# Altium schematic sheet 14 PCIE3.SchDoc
size 420 x 297 mm
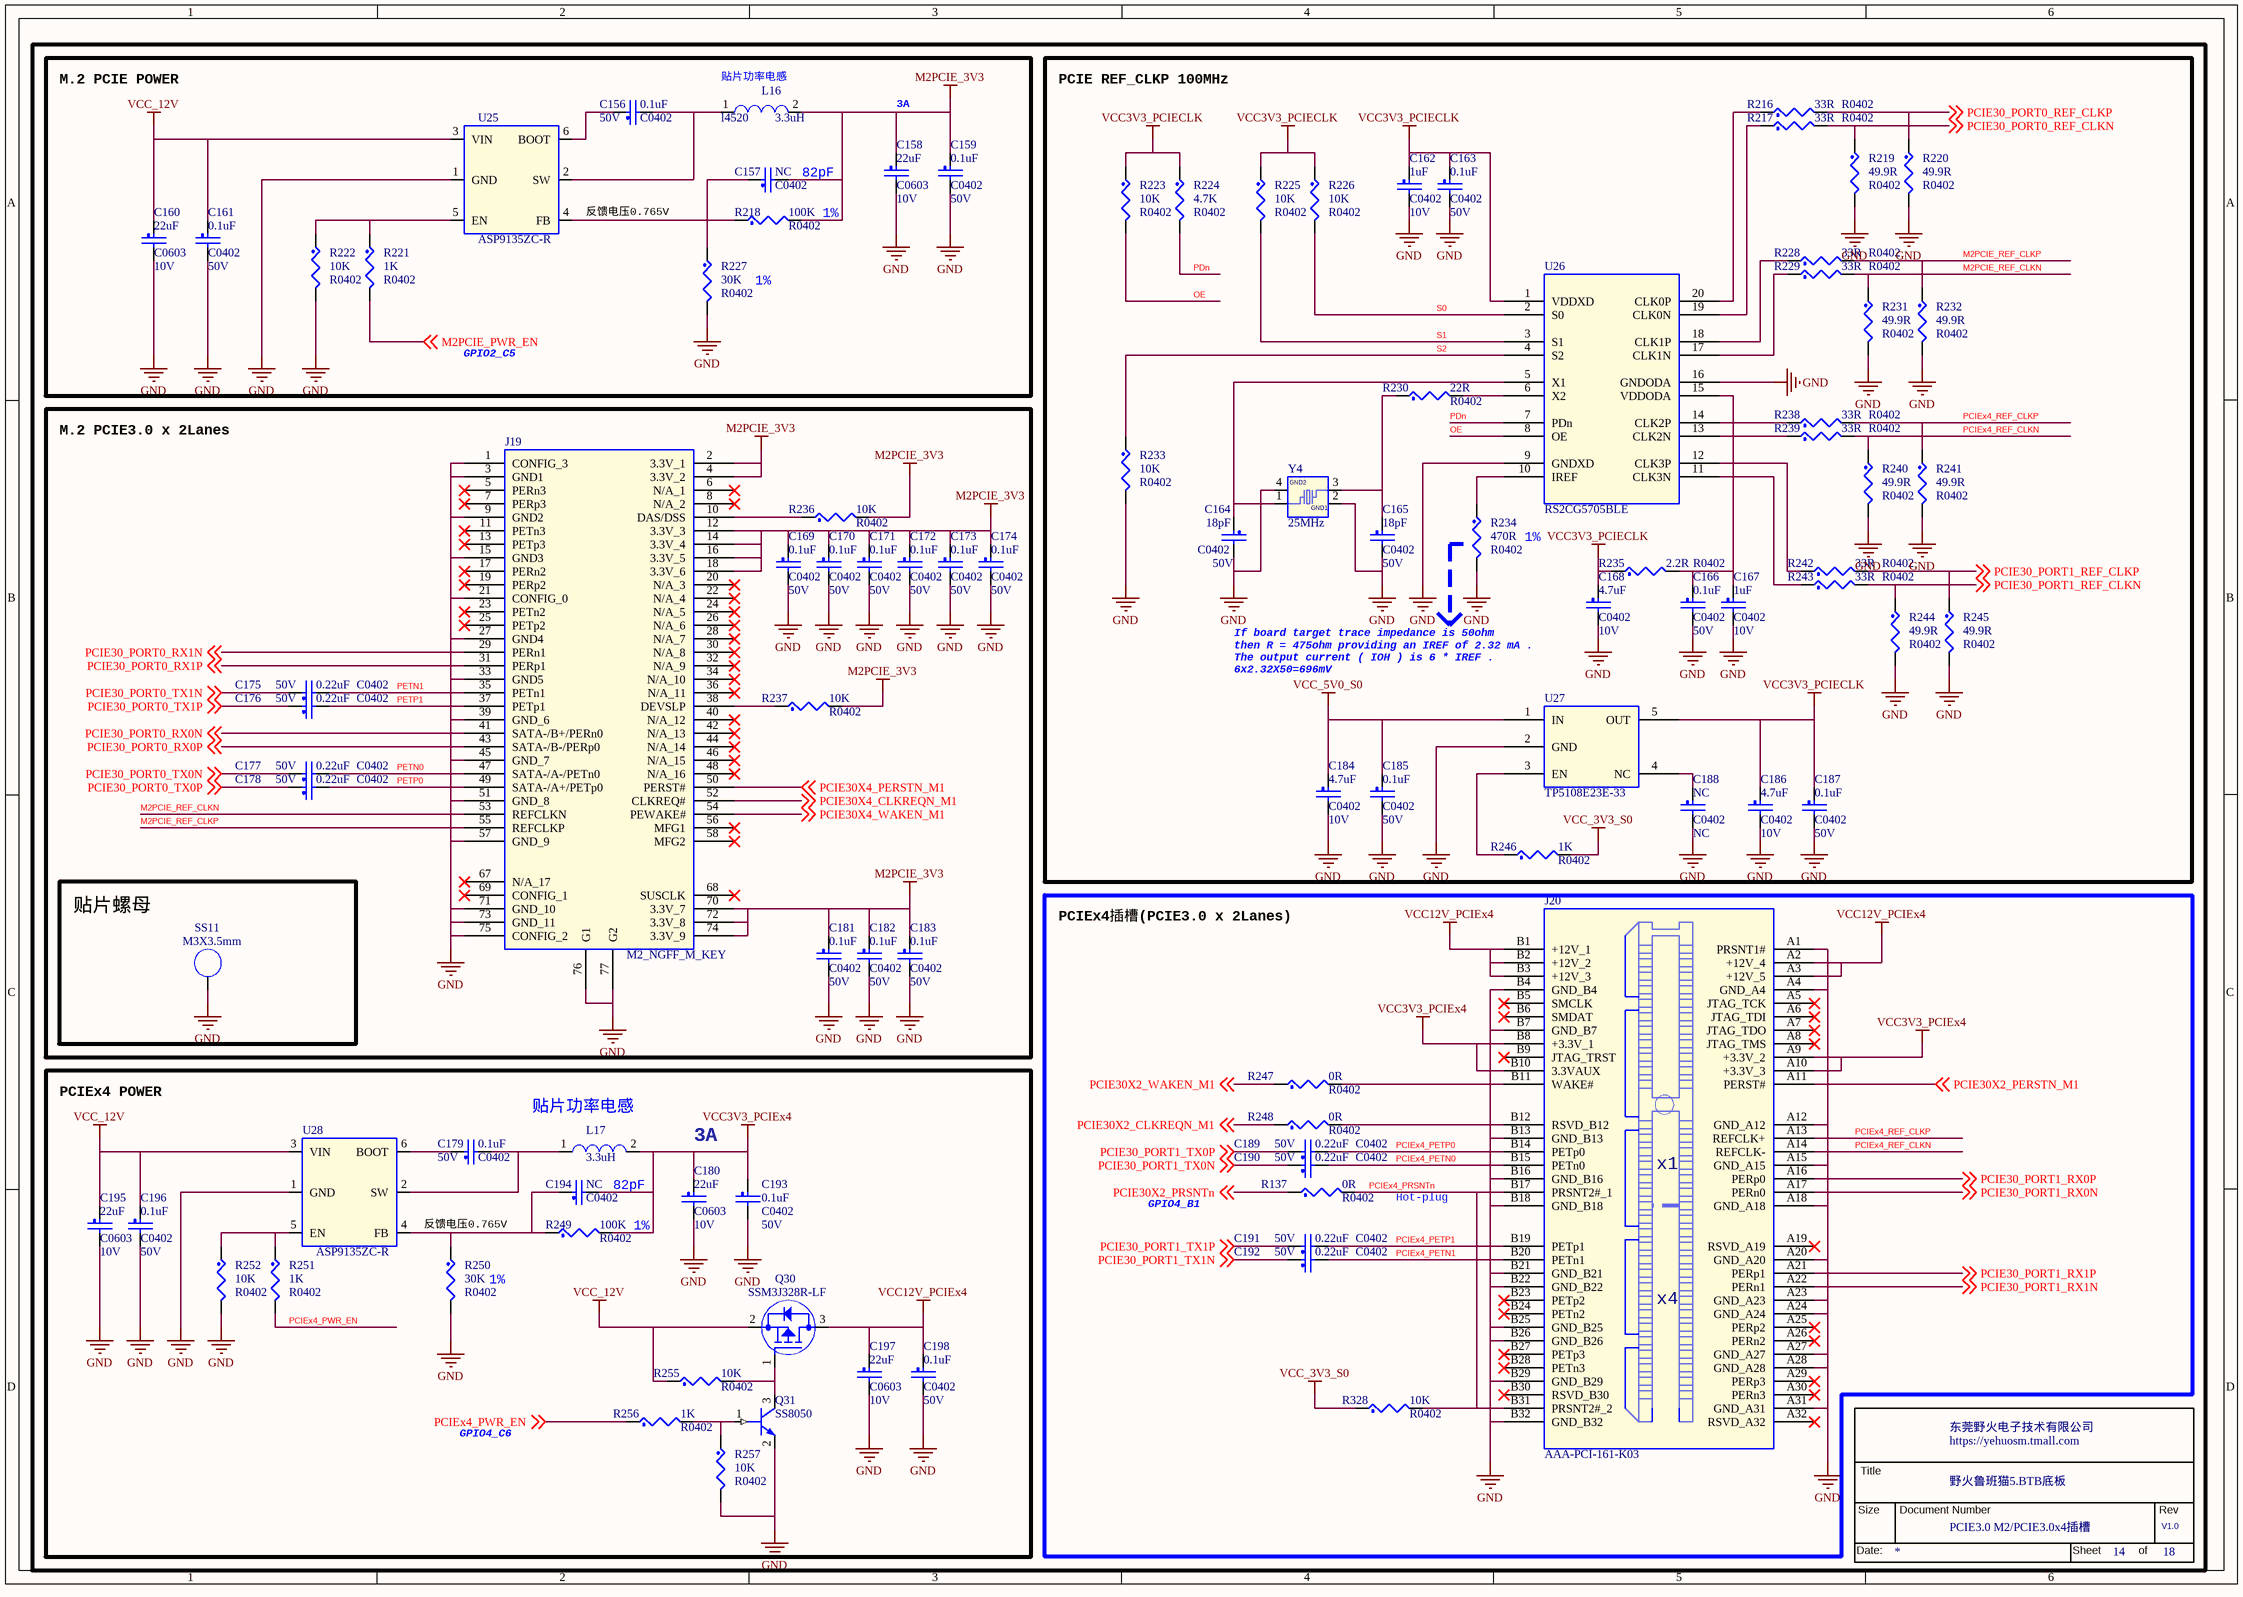
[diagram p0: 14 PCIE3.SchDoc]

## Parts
*  Doc: PCIE3.0 M2/PCIE3.0x4插槽  RevCode: V1.0  Title: 野火鲁班猫5.BTB底板  OrgName: 东莞野火电子技术有限公司  Page Number: 14  Page Count: 18  (hidden comment: TitleBlock_YHSCH)  (graphical)
C156  0.1uF  Voltage: 50V  [C0402]
C157  NC  [C0402]
C158  22uF  Voltage: 10V  [C0603]
C159  0.1uF  Voltage: 50V  [C0402]
C160  22uF  Voltage: 10V  [C0603]
C161  0.1uF  Voltage: 50V  [C0402]
C162  1uF  Voltage: 10V  [C0402]
C163  0.1uF  Voltage: 50V  [C0402]
C164  18pF  Voltage: 50V  [C0402]
C165  18pF  Voltage: 50V  [C0402]
C166  0.1uF  Voltage: 50V  [C0402]
C167  1uF  Voltage: 10V  [C0402]
C168  4.7uF  Voltage: 10V  [C0402]
C169  0.1uF  Voltage: 50V  [C0402]
C170  0.1uF  Voltage: 50V  [C0402]
C171  0.1uF  Voltage: 50V  [C0402]
C172  0.1uF  Voltage: 50V  [C0402]
C173  0.1uF  Voltage: 50V  [C0402]
C174  0.1uF  Voltage: 50V  [C0402]
C175  0.22uF  Voltage: 50V  [C0402]
C176  0.22uF  Voltage: 50V  [C0402]
C177  0.22uF  Voltage: 50V  [C0402]
C178  0.22uF  Voltage: 50V  [C0402]
C179  0.1uF  Voltage: 50V  [C0402]
C180  22uF  Voltage: 10V  [C0603]
C181  0.1uF  Voltage: 50V  [C0402]
C182  0.1uF  Voltage: 50V  [C0402]
C183  0.1uF  Voltage: 50V  [C0402]
C184  4.7uF  Voltage: 10V  [C0402]
C185  0.1uF  Voltage: 50V  [C0402]
C186  4.7uF  Voltage: 10V  [C0402]
C187  0.1uF  Voltage: 50V  [C0402]
C188  NC  [C0402]
C189  0.22uF  Voltage: 50V  [C0402]
C190  0.22uF  Voltage: 50V  [C0402]
C191  0.22uF  Voltage: 50V  [C0402]
C192  0.22uF  Voltage: 50V  [C0402]
C193  0.1uF  Voltage: 50V  [C0402]
C194  NC  [C0402]
C195  22uF  Voltage: 10V  [C0603]
C196  0.1uF  Voltage: 50V  [C0402]
C197  22uF  Voltage: 10V  [C0603]
C198  0.1uF  Voltage: 50V  [C0402]
J19  M2_NGFF_M_KEY  [M2_NGFF_M_KEY]
J20  AAA-PCI-161-K03  [PCIE_64PIN_1R00]
L16  3.3uH  [l4520]
L17  3.3uH  [l4520]
Q30  SSM3J328R-LF  [SOT23]
Q31  SS8050  [SOT23]
R137  0R  [R0402]
R216  33R  [R0402]
R217  33R  [R0402]
R218  100K  [R0402]
R219  49.9R  [R0402]
R220  49.9R  [R0402]
R221  1K  [R0402]
R222  10K  [R0402]
R223  10K  [R0402]
R224  4.7K  [R0402]
R225  10K  [R0402]
R226  10K  [R0402]
R227  30K  [R0402]
R228  33R  [R0402]
R229  33R  [R0402]
R230  22R  [R0402]
R231  49.9R  [R0402]
R232  49.9R  [R0402]
R233  10K  [R0402]
R234  470R  [R0402]
R235  2.2R  [R0402]
R236  10K  [R0402]
R237  10K  [R0402]
R238  33R  [R0402]
R239  33R  [R0402]
R240  49.9R  [R0402]
R241  49.9R  [R0402]
R242  33R  [R0402]
R243  33R  [R0402]
R244  49.9R  [R0402]
R245  49.9R  [R0402]
R246  1K  [R0402]
R247  0R  [R0402]
R248  0R  [R0402]
R249  100K  [R0402]
R250  30K  [R0402]
R251  1K  [R0402]
R252  10K  [R0402]
R255  10K  [R0402]
R256  1K  [R0402]
R257  10K  [R0402]
R328  10K  [R0402]
SS11  M3X3.5mm  [smtso-m3]
U25  ASP9135ZC-R  [SOT23_6]
U26  RS2CG5705BLE  [TSSOP20]
U27  TP5108E23E-33  [SOT23-5]
U28  ASP9135ZC-R  [SOT23_6]
Y4  25MHz  [3225]

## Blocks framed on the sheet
M.2 PCIE POWER: C156-C161 L16 R218 R221 R222 R227 U25
PCIE REF_CLKP 100MHz: C162-C168 C184-C188 R216 R217 R219 R220 R223-R226 R228-R235 R238-R246 U26 U27 Y4
M.2 PCIE3.0 x 2Lanes: C169-C178 C181-C183 J19 R236 R237
贴片螺母: SS11
PCIEx4插槽(PCIE3.0 x 2Lanes): C189-C192 J20 R137 R247 R248 R328
3A: C179 C180 C193-C198 L17 Q30 Q31 R249-R252 R255-R257 U28

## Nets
GND: C158.2 C159.2 C160.2 C161.2 C162.2 C163.2 C164.2 C165.2 C166.2 C167.2 C168.2 C169.2 C170.2 C171.2 C172.2 C173.2 C174.2 C180.2 C181.2 C182.2 C183.2 C184.2 C185.2 C186.2 C187.2 C188.2 C193.2 C195.2 C196.2 C197.2 C198.2 J19.1(CONFIG_3) J19.3(GND1) J19.9(GND2) J19.15(GND3) J19.21(CONFIG_0) J19.27(GND4) J19.33(GND5) J19.39(GND_6) J19.45(GND_7) J19.51(GND_8) J19.57(GND_9) J19.71(GND_10) J19.73(GND_11) J19.75(CONFIG_2) J19.76(G1) J19.77(G2) J20.A1(PRSNT1#) J20.A4(GND_A4) J20.A12(GND_A12) J20.A15(GND_A15) J20.A18(GND_A18) J20.A20(GND_A20) J20.A23(GND_A23) J20.A24(GND_A24) J20.A27(GND_A27) J20.A28(GND_A28) J20.A31(GND_A31) J20.B4(GND_B4) J20.B7(GND_B7) J20.B13(GND_B13) J20.B16(GND_B16) J20.B18(GND_B18) J20.B21(GND_B21) J20.B22(GND_B22) J20.B25(GND_B25) J20.B26(GND_B26) J20.B29(GND_B29) J20.B32(GND_B32) Q31.2(EMITTER) R219.2 R220.2 R222.2 R227.2 R231.2 R232.2 R233.2 R234.2 R240.2 R241.2 R244.2 R245.2 R250.2 R252.2 R257.2 SS11.1(NC_1) U25.1(GND) U26.9(GNDXD) U26.16(GNDODA) U27.2(GND) U28.1(GND) Y4.2(GND1) Y4.4(GND2)
M2PCIE_3V3: C157.2 C158.1 C159.1 C169.1 C170.1 C171.1 C172.1 C173.1 C174.1 C181.1 C182.1 C183.1 J19.2(3.3V_1) J19.4(3.3V_2) J19.12(3.3V_3) J19.14(3.3V_4) J19.16(3.3V_5) J19.18(3.3V_6) J19.70(3.3V_7) J19.72(3.3V_8) J19.74(3.3V_9) L16.2 R218.2 R236.2 R237.2
VCC3V3_PCIECLK: C162.1 C163.1 C168.1 C186.1 C187.1 R223.1 R224.1 R225.1 R226.1 R235.1 U26.1(VDDXD) U27.5(OUT)
VCC3V3_PCIEx4: C180.1 C193.1 C194.2 J20.A9(+3.3V_2) J20.A10(+3.3V_3) J20.B8(+3.3V_1) J20.B10(3.3VAUX) L17.2 R249.2
VCC12V_PCIEx4: C197.1 C198.1 J20.A2(+12V_4) J20.A3(+12V_5) J20.B1(+12V_1) J20.B2(+12V_2) J20.B3(+12V_3) Q30.3(DRAIN)
VCC_3V3_S0: R246.2 R328.1
VCC_5V0_S0: C184.1 C185.1 U27.1(IN)
VCC_12V: C160.1 C161.1 C195.1 C196.1 Q30.2(SOURCE) R255.1 U25.3(VIN) U28.3(VIN)
M2PCIE_PWR_EN: R221.2 ; off-sheet M2PCIE_PWR_EN
M2PCIE_REF_CLKN: J19.53(REFCLKN) R229.2 R231.1
M2PCIE_REF_CLKP: J19.55(REFCLKP) R228.2 R232.1
OE: R223.2 U26.8(OE)
PCIE30_PORT0_REF_CLKN: R217.2 R219.1 ; off-sheet PCIE30_PORT0_REF_CLKN
PCIE30_PORT0_REF_CLKP: R216.2 R220.1 ; off-sheet PCIE30_PORT0_REF_CLKP
PCIE30_PORT0_RX0N: J19.41(SATA-/B+/PERn0) ; off-sheet PCIE30_PORT0_RX0N
PCIE30_PORT0_RX0P: J19.43(SATA-/B-/PERp0) ; off-sheet PCIE30_PORT0_RX0P
PCIE30_PORT0_RX1N: J19.29(PERn1) ; off-sheet PCIE30_PORT0_RX1N
PCIE30_PORT0_RX1P: J19.31(PERp1) ; off-sheet PCIE30_PORT0_RX1P
PCIE30_PORT0_TX0N: C177.1 ; off-sheet PCIE30_PORT0_TX0N
PCIE30_PORT0_TX0P: C178.1 ; off-sheet PCIE30_PORT0_TX0P
PCIE30_PORT0_TX1N: C175.1 ; off-sheet PCIE30_PORT0_TX1N
PCIE30_PORT0_TX1P: C176.1 ; off-sheet PCIE30_PORT0_TX1P
PCIE30_PORT1_REF_CLKN: R243.2 R244.1 ; off-sheet PCIE30_PORT1_REF_CLKN
PCIE30_PORT1_REF_CLKP: R242.2 R245.1 ; off-sheet PCIE30_PORT1_REF_CLKP
PCIE30_PORT1_RX0N: J20.A17(PERn0) ; off-sheet PCIE30_PORT1_RX0N
PCIE30_PORT1_RX0P: J20.A16(PERp0) ; off-sheet PCIE30_PORT1_RX0P
PCIE30_PORT1_RX1N: J20.A22(PERn1) ; off-sheet PCIE30_PORT1_RX1N
PCIE30_PORT1_RX1P: J20.A21(PERp1) ; off-sheet PCIE30_PORT1_RX1P
PCIE30_PORT1_TX0N: C190.1 ; off-sheet PCIE30_PORT1_TX0N
PCIE30_PORT1_TX0P: C189.1 ; off-sheet PCIE30_PORT1_TX0P
PCIE30_PORT1_TX1N: C192.1 ; off-sheet PCIE30_PORT1_TX1N
PCIE30_PORT1_TX1P: C191.1 ; off-sheet PCIE30_PORT1_TX1P
PCIE30X2_CLKREQN_M1: R248.1 ; off-sheet PCIE30X2_CLKREQN_M1
PCIE30X2_PERSTN_M1: J20.A11(PERST#) ; off-sheet PCIE30X2_PERSTN_M1
PCIE30X2_PRSNTn: R137.1 ; off-sheet PCIE30X2_PRSNTn
PCIE30X2_WAKEN_M1: R247.1 ; off-sheet PCIE30X2_WAKEN_M1
PCIE30X4_CLKREQN_M1: J19.52(CLKREQ#) ; off-sheet PCIE30X4_CLKREQN_M1
PCIE30X4_PERSTN_M1: J19.50(PERST#) ; off-sheet PCIE30X4_PERSTN_M1
PCIE30X4_WAKEN_M1: J19.54(PEWAKE#) ; off-sheet PCIE30X4_WAKEN_M1
PCIEx4_PETN0: C190.2 J20.B15(PETn0)
PCIEx4_PETN1: C192.2 J20.B20(PETn1)
PCIEx4_PETP0: C189.2 J20.B14(PETp0)
PCIEx4_PETP1: C191.2 J20.B19(PETp1)
PCIEx4_PRSNTn: J20.B17(PRSNT2#_1) J20.B31(PRSNT2#_2) R137.2 R328.2
PCIEx4_PWR_EN: R251.2 R256.1 ; off-sheet PCIEx4_PWR_EN
PCIEx4_REF_CLKN: J20.A14(REFCLK-) R239.2 R240.1
PCIEx4_REF_CLKP: J20.A13(REFCLK+) R238.2 R241.1
PDn: R224.2 U26.7(PDn)
PETN0: C177.2 J19.47(SATA-/A-/PETn0)
PETN1: C175.2 J19.35(PETn1)
PETP0: C178.2 J19.49(SATA-/A+/PETp0)
PETP1: C176.2 J19.37(PETp1)
S0: R226.2 U26.2(S0)
S1: R225.2 U26.3(S1)
S2: R233.1 U26.4(S2)
NetC156_1: C156.1 U25.6(BOOT)
NetC156_2: C156.2 L16.1 U25.2(SW)
NetC157_1: C157.1 R218.1 R227.1 U25.4(FB)
NetC164_1: C164.1 U26.5(X1) Y4.1
NetC165_1: C165.1 R230.1 Y4.3
NetC166_1: C166.1 C167.1 R235.2 U26.15(VDDODA)
NetC179_1: C179.1 U28.6(BOOT)
NetC179_2: C179.2 L17.1 U28.2(SW)
NetC188_1: C188.1 U27.4(NC)
NetC194_1: C194.1 R249.1 R250.1 U28.4(FB)
NetJ19_10: J19.10(DAS/DSS) R236.1
NetJ19_38: J19.38(DEVSLP) R237.1
NetJ20_B11: J20.B11(WAKE#) R247.2
NetJ20_B12: J20.B12(RSVD_B12) R248.2
NetQ30_1: Q30.1(GATE) Q31.3(COLLECTOR) R255.2
NetQ31_1: Q31.1(BASE) R256.2 R257.1
NetR216_1: R216.1 U26.20(CLK0P)
NetR217_1: R217.1 U26.19(CLK0N)
NetR221_1: R221.1 R222.1 U25.5(EN)
NetR228_1: R228.1 U26.18(CLK1P)
NetR229_1: R229.1 U26.17(CLK1N)
NetR230_2: R230.2 U26.6(X2)
NetR234_1: R234.1 U26.10(IREF)
NetR238_1: R238.1 U26.14(CLK2P)
NetR239_1: R239.1 U26.13(CLK2N)
NetR242_1: R242.1 U26.12(CLK3P)
NetR243_1: R243.1 U26.11(CLK3N)
NetR246_1: R246.1 U27.3(EN)
NetR251_1: R251.1 R252.1 U28.5(EN)

Not connected (* = marked no-connect by the designer): J19 5(PERn3)* 6(N/A_1)* 7(PERp3)* 8(N/A_2)* 11(PETn3)* 13(PETp3)* 17(PERn2)* 19(PERp2)* 20(N/A_3)* 22(N/A_4)* 23(PETn2)* 24(N/A_5)* 25(PETp2)* 26(N/A_6)* 28(N/A_7)* 30(N/A_8)* 32(N/A_9)* 34(N/A_10)* 36(N/A_11)* 40(N/A_12)* 42(N/A_13)* 44(N/A_14)* 46(N/A_15)* 48(N/A_16)* 56(MFG1)* 58(MFG2)* 67(N/A_17)* 68(SUSCLK)* 69(CONFIG_1)*; J20 A5(JTAG_TCK)* A6(JTAG_TDI)* A7(JTAG_TDO)* A8(JTAG_TMS)* A19(RSVD_A19)* A25(PERp2)* A26(PERn2)* A29(PERp3)* A30(PERn3)* A32(RSVD_A32)* B5(SMCLK)* B6(SMDAT)* B9(JTAG_TRST)* B23(PETp2)* B24(PETn2)* B27(PETp3)* B28(PETn3)* B30(RSVD_B30)*

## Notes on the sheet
- (near L16) 贴片功率电感
- 3A
- 82pF
- (near U25) 反馈电压0.765V
- 1%
- GPIO2_C5
- If board target trace impedance is 50ohm
  then R = 475ohm providing an IREF of 2.32 mA .
  The output current ( IOH ) is 6 * IREF .
  6x2.32X50=696mV
- PCIEx4 POWER
- (near L17) 贴片功率电感
- GPIO4_B1
- Hot-plug
- 反馈电压0.765V
- (near R250) 1%
- GPIO4_C6

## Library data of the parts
* = TitleBlock_YHSCH: Cage Code: 1
C156 C159 C161 C166 C181-C183 C187 C193 C196 = CAP_NP: CLASS: DISCRETE; 规格: 贴片电容0.1uF 10% 50V X5R 0402; 规格编号: 0402X104K500NT; 条码: EBF29060118; 品牌: 风华; 类别: 贴片电容0402; 规格书: 风华电容.pdf; 价格: 0.029826; 生命周期: 量产
C157 C188 = CAP_NP: CLASS: DISCRETE; 类别: 贴片电容0402; 条码: EBF29060149; 规格: 贴片电容NC 预留
C158 C180 C195 = CAP_NP: CLASS: DISCRETE; 生命周期: 量产; 价格: 0.078818; 规格书: 三星电容.pdf; 类别: 贴片电容0603; 品牌: 三星; 条码: EBF29060163; 规格编号: CL10A226MP8NUNE; 规格: 贴片电容22uF 20% 10V X5R 0603
C160 C197 = CAP_NP: CLASS: DISCRETE; 规格: 贴片电容22uF 20% 10V X5R 0603; 规格编号: CL10A226MP8NUNE; 条码: EBF29060163; 品牌: 三星; 类别: 贴片电容0603; 规格书: 三星电容.pdf; 价格: 0.078818; 生命周期: 量产
C162 = CAP_NP: CLASS: DISCRETE; 规格: 贴片电容1uF 10% 10V X5R 0402; 规格编号: 0402X105K100NT; 条码: EBF29060121; 品牌: 风华; 类别: 贴片电容0402; 规格书: 风华电容.pdf; 价格: 0.01191; 生命周期: 量产
C163 C169-C174 C179 C185 C198 = CAP_NP: CLASS: DISCRETE; 生命周期: 量产; 价格: 0.029826; 规格书: 风华电容.pdf; 类别: 贴片电容0402; 品牌: 风华; 条码: EBF29060118; 规格编号: 0402X104K500NT; 规格: 贴片电容0.1uF 10% 50V X5R 0402
C164 = CAP_NP: CLASS: DISCRETE; 生命周期: 量产; 价格: 0.00515; 规格书: 风华电容.pdf; 类别: 贴片电容0402; 品牌: 风华; 条码: EBF29060235; 规格编号: 0402CG180J500NT; 规格: 贴片电容18pF 5% 50V C0G 0402
C165 = CAP_NP: CLASS: DISCRETE; 规格: 贴片电容18pF 5% 50V C0G 0402; 规格编号: 0402CG180J500NT; 条码: EBF29060235; 品牌: 风华; 类别: 贴片电容0402; 规格书: 风华电容.pdf; 价格: 0.00515; 生命周期: 量产
C167 = CAP_NP: CLASS: DISCRETE; 生命周期: 量产; 价格: 0.01191; 规格书: 风华电容.pdf; 类别: 贴片电容0402; 品牌: 风华; 条码: EBF29060121; 规格编号: 0402X105K100NT; 规格: 贴片电容1uF 10% 10V X5R 0402
C168 C186 = CAP_NP: CLASS: DISCRETE; 规格: 贴片电容4.7uF 10% 10V X5R 0402; 规格编号: CC0402KRX5R6BB475; 条码: EBF29060248; 品牌: 国巨; 类别: 贴片电容0402; 规格书: 国巨-贴片电容.pdf; 价格: 0.059058; 生命周期: 量产
C175-C178 = CAP_NP: CLASS: DISCRETE; 生命周期: 量产; 价格: 0.074942; 规格书: 太诱-贴片电容.pdf; 类别: 贴片电容0402; 品牌: 太诱; 条码: EBF29060266; 规格编号: UMK105BJ224MV-F; 规格: 贴片电容0.22uF 20% 50V X5R 0402
C184 = CAP_NP: CLASS: DISCRETE; 生命周期: 量产; 价格: 0.059058; 规格书: 国巨-贴片电容.pdf; 类别: 贴片电容0402; 品牌: 国巨; 条码: EBF29060248; 规格编号: CC0402KRX5R6BB475; 规格: 贴片电容4.7uF 10% 10V X5R 0402
C189-C192 = CAP_NP: CLASS: DISCRETE; 规格: 贴片电容0.22uF 20% 50V X5R 0402; 规格编号: UMK105BJ224MV-F; 条码: EBF29060266; 品牌: 太诱; 类别: 贴片电容0402; 规格书: 太诱-贴片电容.pdf; 价格: 0.074942; 生命周期: 量产
C194 = CAP_NP: CLASS: DISCRETE; 规格: 贴片电容NC 预留; 条码: EBF29060149; 类别: 贴片电容0402
J19 = M2_NGFF_M_KEY: 规格: M.2NGFF高度5.5MMM.2连接器镀金30UMKEY67PIN; 条码: EBF29040083; 类别: 金手指连接器; 规格书: M.2NGFF-M-67PIN.pdf; 生命周期: 量产
J20 = PCIEX4_64P: 备注: RK3588 BTB底板; 生命周期: 量产; 规格书: 嘉澤端子_AAA-PCI-161-K03.pdf; 类别: 金手指连接器; 品牌: 嘉澤端子; 条码: EBFCIS230725213659; 规格: PCIEX4连接器 64P 插件
L16 L17 = IND: CLASS: DISCRETE; 规格: 贴片电感3.3uH ±20% 3A 直流电阻69mΩ; 条码: EBF29050040; 品牌: 台庆; 类别: 贴片电感0402; 规格书: 台庆-功率电感.pdf; 生命周期: 量产; 规格编号: TMPC0402HP-3R3MG-Z02; 价格: 1.5992
Q30 = MOSFET_P: CLASS: IC; 规格: P沟道MOS 导通电阻29.8mΩ 电流3A 1.5V可驱动; 规格编号: SSM3J328R LF; 条码: EBF29280008; 品牌: 东芝; 类别: P-MOS; 规格书: SSM3J328R-LF.pdf; 价格: 0.447836; 生命周期: 量产; 丝印: KFH-XXX
Q31 = NPN: CLASS: IC; 规格: 贴片三极管SS8050 集电极电流1.5A 额定功率300mW NPN; 条码: EBF29090001; 品牌: 江苏长电; 类别: 贴片三极管SOT-23; 规格书: 江苏长电-SS8050Y1.pdf; 价格: 0.086744; 生命周期: 量产; 丝印: Y1
R137 R247 R248 = RES: CLASS: DISCRETE; 规格: 贴片电阻0R 1% 1/16W 0402; 规格编号: RI0402L000FT; 条码: EBF29070049; 品牌: 合科泰; 类别: 贴片电阻0402; 规格书: 合科泰-RI系列电阻.pdf; 生命周期: 量产
R216 R217 R228 R229 R242 R243 = RES: CLASS: DISCRETE; 生命周期: 量产; 价格: 0.002158; 规格书: 厚声-无铅厚膜电阻.pdf; 类别: 贴片电阻0402; 品牌: 厚声; 条码: EBF29070187; 规格编号: 0402WGF330JTCE; 规格: 贴片电阻33R 1% 1/16W 0402
R218 = RES: CLASS: DISCRETE; 生命周期: 量产; 规格书: 合科泰-RI系列电阻.pdf; 类别: 贴片电阻0402; 品牌: 合科泰; 条码: EBF29070054; 规格编号: RI0402L1003FT; 规格: 贴片电阻100K 1% 1/16W 0402
R219 R220 R240 R241 R244 R245 = RES: CLASS: DISCRETE; 生命周期: 量产; 价格: 0.002703; 规格书: 厚声-无铅厚膜电阻.pdf; 类别: 贴片电阻0402; 品牌: 厚声; 条码: EBF29070059; 规格编号: 0402WGF499JTCE; 规格: 贴片电阻49.9R 1% 1/16W 0402
R221 R251 = RES: CLASS: DISCRETE; 规格: 贴片电阻1K 1% 1/16W 0402; 规格编号: RI0402L1001FT; 条码: EBF29070050; 品牌: 合科泰; 类别: 贴片电阻0402; 规格书: 合科泰-RI系列电阻.pdf; 生命周期: 量产
R222 R223 R225 R226 R233 R236 R237 R252 = RES: CLASS: DISCRETE; 生命周期: 量产; 价格: 0.002773; 规格书: 厚声-无铅厚膜电阻.pdf; 类别: 贴片电阻0402; 品牌: 厚声; 条码: EBF29070046; 规格编号: 0402WGF1002TCE; 规格: 贴片电阻10K 1% 1/16W 0402
R224 = RES: CLASS: DISCRETE; 规格: 贴片电阻4.7K 1% 1/16W 0402; 规格编号: RI0402L4701FT; 条码: EBF29070047; 品牌: 合科泰; 类别: 贴片电阻0402; 规格书: 合科泰-RI系列电阻.pdf; 生命周期: 量产
R227 = RES: CLASS: DISCRETE; 生命周期: 量产; 规格书: 合科泰-RI系列电阻.pdf; 类别: 贴片电阻0402; 品牌: 合科泰; 条码: EBF29070048; 规格编号: RI0402L3002FT; 规格: 贴片电阻30K 1% 1/16W 0402
R230 = RES: CLASS: DISCRETE; 规格: 贴片电阻22R 1% 1/16W 0402; 规格编号: RI0402L22R0FT; 条码: EBF29070181; 品牌: 合科泰; 类别: 贴片电阻0402; 规格书: 合科泰-RI系列电阻.pdf; 生命周期: 量产
R231 R232 = RES: CLASS: DISCRETE; 规格: 贴片电阻49.9R 1% 1/16W 0402; 规格编号: 0402WGF499JTCE; 条码: EBF29070059; 品牌: 厚声; 类别: 贴片电阻0402; 规格书: 厚声-无铅厚膜电阻.pdf; 价格: 0.002703; 生命周期: 量产
R234 = RES: CLASS: DISCRETE; 生命周期: 量产; 价格: 0.002728; 规格书: 厚声-无铅厚膜电阻.pdf; 类别: 贴片电阻0402; 品牌: 厚声; 条码: EBF29070284; 规格编号: 0402WGF4700TCE; 规格: 贴片电阻470R 1% 1/16W 0402
R235 = RES: CLASS: DISCRETE; 规格: 贴片电阻2.2R 1% 1/16W 0402; 规格编号: 0402WGF220KTCE; 条码: EBF29070280; 品牌: 厚声; 类别: 贴片电阻0402; 规格书: 厚声-无铅厚膜电阻.pdf; 价格: 0.003072; 生命周期: 量产
R238 R239 = RES: CLASS: DISCRETE; 规格: 贴片电阻33R 1% 1/16W 0402; 规格编号: 0402WGF330JTCE; 条码: EBF29070187; 品牌: 厚声; 类别: 贴片电阻0402; 规格书: 厚声-无铅厚膜电阻.pdf; 价格: 0.002158; 生命周期: 量产
R246 R256 = RES: CLASS: DISCRETE; 生命周期: 量产; 规格书: 合科泰-RI系列电阻.pdf; 类别: 贴片电阻0402; 品牌: 合科泰; 条码: EBF29070050; 规格编号: RI0402L1001FT; 规格: 贴片电阻1K 1% 1/16W 0402
R249 = RES: CLASS: DISCRETE; 规格: 贴片电阻100K 1% 1/16W 0402; 规格编号: RI0402L1003FT; 条码: EBF29070054; 品牌: 合科泰; 类别: 贴片电阻0402; 规格书: 合科泰-RI系列电阻.pdf; 生命周期: 量产
R250 = RES: CLASS: DISCRETE; 规格: 贴片电阻30K 1% 1/16W 0402; 规格编号: RI0402L3002FT; 条码: EBF29070048; 品牌: 合科泰; 类别: 贴片电阻0402; 规格书: 合科泰-RI系列电阻.pdf; 生命周期: 量产
R255 R257 R328 = RES: CLASS: DISCRETE; 规格: 贴片电阻10K 1% 1/16W 0402; 规格编号: 0402WGF1002TCE; 条码: EBF29070046; 品牌: 厚声; 类别: 贴片电阻0402; 规格书: 厚声-无铅厚膜电阻.pdf; 价格: 0.002773; 生命周期: 量产
SS11 = SPACER: CLASS: IC; 规格: SMT贴片螺母M3 台阶高度1.53mm 台阶外径：4.09mm 螺柱长度：3.5MM; 规格编号: SMTSO3035CTJ; 条码: EBF29410007; 品牌: 雄和远景; 类别: 贴片螺母; 规格书: Sinhoo电路板表贴螺母柱_PCB_SMT_Nuts.pdf; 生命周期: 量产
U25 = TP6327GS6: 生命周期: 量产; 规格书: 安森德_ASP9135ZC-R.pdf; 类别: 电源管理-DCDC; 品牌: 安森德; 条码: EBFCIS240710113940; 规格: DC-DC电源芯片 可输出电流 3A 开关工作频率 600kHz 输出类型 ADJ 输入电压范围：4V-18V; 备注: RK3566金手指与BTB底板替换物料
U26 = PI6C557-05BLE: 备注: 通用; 生命周期: 量产; 规格书: 锐星微_RS2CG5705BLE.pdf; 类别: 时钟信号发生器; 品牌: 锐星微; 条码: EBFCIS240814173115; 规格: PCIe Gen 3 时钟发生器 输出通道：4通道 工作电压3.0~3.6V 输入频率：25MHz 最大输出频率：200MHz
U27 = LDO_PT5108: 规格: 低压差LDO 最高7V 输出3.3V 最大电流500mA 压差300mV@(200mA) 低噪声 高PSRR; 条码: EBF29110067; 品牌: 台舟; 类别: 电源管理-LDO; 规格书: 台舟TP5108E.pdf; 价格: 0.48864; 生命周期: 量产
U28 = TP6327GS6: 规格: DC-DC电源芯片 可输出电流 3A 开关工作频率 600kHz 输出类型 ADJ 输入电压范围：4V-18V; 条码: EBFCIS240710113940; 品牌: 安森德; 类别: 电源管理-DCDC; 规格书: 安森德_ASP9135ZC-R.pdf; 生命周期: 量产; 备注: RK3566金手指与BTB底板替换物料
Y4 = CRYSTAL_4P: CLASS: IC; 规格: 无源晶振25MHZ 50Ω 16pF 3225; 规格编号: X322525MQB4SI; 条码: EBF29100005; 品牌: 扬兴科技; 类别: 贴片晶振 3225; 规格书: 扬兴科技-25MHZ.pdf; 价格: 0.385846; 生命周期: 量产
